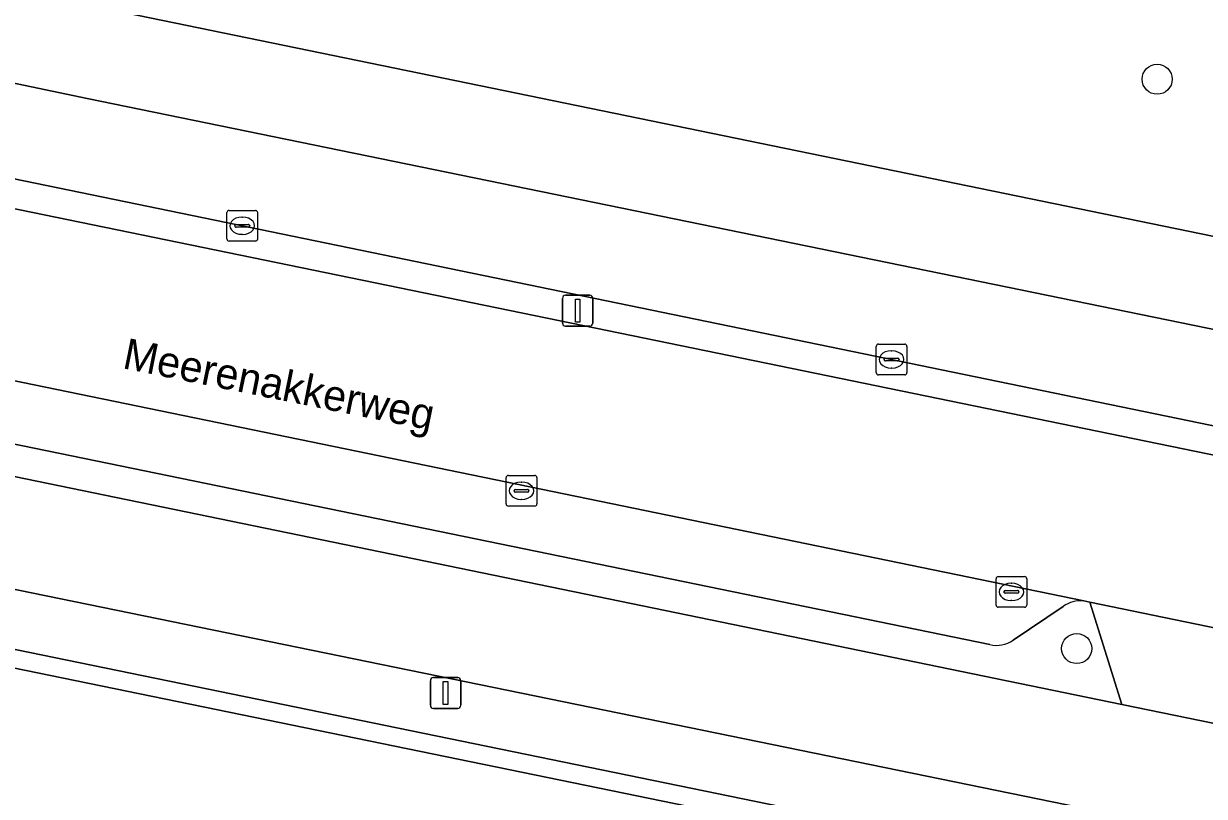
# Model space of a CAD drawing. Extents: x 157692 to 159674, y 381452 to 383291.
# Drawn here: x 158620.46 to 158658.83, y 382068.81 to 382093.93 of the extents above; entities that cross this region are included whole.
import ezdxf

# ---------------------------------------------------------------- set-up
doc = ezdxf.new("R2010")
doc.units = 0
for name, color, linetype in [('IMGEO_Berm_groen', 7, 'Continuous'), ('IMGEO_Boom', 7, 'Continuous'), ('IMGEO_Erf', 7, 'Continuous'), ('IMGEO_Fietspad_gesloten', 7, 'Continuous'), ('IMGEO_Groenvoorziening', 7, 'Continuous'), ('IMGEO_Haag', 7, 'Continuous'), ('IMGEO_Kolk', 7, 'Continuous'), ('IMGEO_Lichtmast', 7, 'Continuous'), ('IMGEO_Openbare_ruimte_label', 7, 'Continuous'), ('IMGEO_Parkeervlak_open', 7, 'Continuous'), ('IMGEO_Rijbaan_lokaal_open', 7, 'Continuous'), ('IMGEO_Rijbaan_regionaal_gesloten', 7, 'Continuous'), ('IMGEO_Voetpad_open', 7, 'Continuous')]:
    doc.layers.add(name, color=color, linetype=linetype)

msp = doc.modelspace()

# ---------------------------------------------------------------- linework, layer by layer
at = {"layer": 'IMGEO_Berm_groen'}
for points in [[(158595.092, 382100.086), (158601.14, 382098.944), (158779.77, 382062.223), (158785.616, 382060.813), (158789.108, 382059.781)], [(158778.07, 382056.314), (158773.956, 382057.298), (158711.762, 382070.015), (158600.841, 382092.865), (158585.035, 382095.717)], [(158599.236, 382092.209), (158771.914, 382056.729), (158774.468, 382056.03)], [(158599.702, 382084.466), (158599.637, 382084.492), (158599.36, 382083.49), (158656.145, 382071.8), (158655.104, 382075.124), (158654.912, 382075.163)], [(158651.862, 382073.744), (158599.702, 382084.466)], [(158654.239, 382074.984), (158652.612, 382073.887)]]:
    msp.add_lwpolyline(points, dxfattribs=at)
for centre, radius, start, end in [((158654.812, 382074.184), 0.984, 84.1681, 125.6206), ((158652.074, 382074.672), 0.952, 257.1467, 304.443)]:
    msp.add_arc(centre, radius, start, end, dxfattribs=at)
at = {"layer": 'IMGEO_Boom'}
for centre in [(158657.295, 382092.122), (158654.68, 382073.617)]:
    msp.add_circle(centre, 0.489, dxfattribs=at)
at = {"layer": 'IMGEO_Erf'}
msp.add_lwpolyline([(158656.531, 382065.514), (158574.936, 382082.265)], dxfattribs=at)
at = {"layer": 'IMGEO_Fietspad_gesloten'}
for points in [[(158776.64, 382046.995), (158774.025, 382047.607), (158748.896, 382052.715), (158732.567, 382056.096), (158710.713, 382060.669), (158694.964, 382063.831), (158656.145, 382071.8), (158599.36, 382083.49), (158578.485, 382087.788), (158553.523, 382092.644), (158551.737, 382093.049), (158548.395, 382093.597), (158547.676, 382093.718)], [(158533.524, 382092.807), (158567.173, 382086.396), (158657.056, 382067.984), (158692.348, 382060.756), (158733.578, 382052.258), (158746.373, 382049.67), (158773.852, 382044.005)]]:
    msp.add_lwpolyline(points, dxfattribs=at)
at = {"layer": 'IMGEO_Groenvoorziening'}
msp.add_lwpolyline([(158539.307, 382077.53), (158544.304, 382079.926), (158549.351, 382081.923), (158553.579, 382082.999), (158557.322, 382083.532), (158561.047, 382084.02), (158565.823, 382083.768), (158570.839, 382083.106), (158574.936, 382082.265), (158656.531, 382065.514), (158658.251, 382065.165), (158658.369, 382065.753), (158656.651, 382066.102), (158575.057, 382082.853), (158570.941, 382083.698), (158565.878, 382084.366), (158561.024, 382084.622), (158557.24, 382084.126), (158553.463, 382083.589), (158549.165, 382082.495), (158544.064, 382080.476), (158539.061, 382078.078)], dxfattribs=at)
at = {"layer": 'IMGEO_Haag'}
msp.add_lwpolyline([(158539.307, 382077.53), (158544.304, 382079.926), (158549.351, 382081.923), (158553.579, 382082.999), (158557.322, 382083.532), (158561.047, 382084.02), (158565.823, 382083.768), (158570.839, 382083.106), (158574.936, 382082.265), (158656.531, 382065.514), (158658.251, 382065.165), (158658.369, 382065.753), (158656.651, 382066.102), (158575.057, 382082.853), (158570.941, 382083.698), (158565.878, 382084.366), (158561.024, 382084.622), (158557.24, 382084.126), (158553.463, 382083.589), (158549.165, 382082.495), (158544.064, 382080.476), (158539.061, 382078.078)], dxfattribs=at)
at = {"layer": 'IMGEO_Kolk'}
for p, q in [((158627.065, 382086.934), (158627.065, 382087.786)), ((158627.14, 382087.86), (158627.992, 382087.86)), ((158628.066, 382087.786), (158628.066, 382086.934)), ((158627.324, 382087.354), (158627.324, 382087.366)), ((158627.367, 382087.403), (158627.765, 382087.403)), ((158627.553, 382087.64), (158627.578, 382087.64)), ((158627.808, 382087.366), (158627.808, 382087.354)), ((158627.762, 382087.317), (158627.364, 382087.317)), ((158627.576, 382087.08), (158627.551, 382087.08)), ((158627.992, 382086.86), (158627.14, 382086.86)), ((158648.239, 382083.513), (158649.091, 382083.513)), ((158648.164, 382082.587), (158648.164, 382083.439)), ((158648.652, 382083.293), (158648.677, 382083.293)), ((158649.165, 382083.439), (158649.165, 382082.587)), ((158648.423, 382083.007), (158648.423, 382083.019)), ((158648.861, 382082.97), (158648.463, 382082.97)), ((158648.466, 382083.056), (158648.864, 382083.056)), ((158648.907, 382083.019), (158648.907, 382083.007)), ((158649.091, 382082.513), (158648.239, 382082.513)), ((158648.675, 382082.733), (158648.65, 382082.733)), ((158636.137, 382078.32), (158636.137, 382079.172)), ((158636.212, 382079.246), (158637.064, 382079.246)), ((158636.625, 382079.026), (158636.65, 382079.026)), ((158637.138, 382079.172), (158637.138, 382078.32)), ((158636.396, 382078.74), (158636.396, 382078.752)), ((158636.834, 382078.703), (158636.436, 382078.703)), ((158636.439, 382078.789), (158636.837, 382078.789)), ((158636.88, 382078.752), (158636.88, 382078.74)), ((158637.064, 382078.246), (158636.212, 382078.246)), ((158636.648, 382078.466), (158636.623, 382078.466)), ((158652.058, 382075.031), (158652.058, 382075.883)), ((158652.133, 382075.957), (158652.985, 382075.957)), ((158653.059, 382075.883), (158653.059, 382075.031)), ((158652.317, 382075.451), (158652.317, 382075.463)), ((158652.36, 382075.5), (158652.758, 382075.5)), ((158652.546, 382075.737), (158652.571, 382075.737)), ((158652.801, 382075.463), (158652.801, 382075.451)), ((158652.755, 382075.414), (158652.357, 382075.414)), ((158652.569, 382075.177), (158652.544, 382075.177)), ((158652.985, 382074.957), (158652.133, 382074.957))]:
    msp.add_line(p, q, dxfattribs=at)
for points in [[(158627.065, 382086.934), (158627.065, 382087.786)], [(158627.14, 382087.86), (158627.992, 382087.86)], [(158628.066, 382087.786), (158628.066, 382086.934)], [(158627.992, 382086.86), (158627.14, 382086.86)], [(158648.239, 382083.513), (158649.091, 382083.513)], [(158648.164, 382082.587), (158648.164, 382083.439)], [(158649.165, 382083.439), (158649.165, 382082.587)], [(158649.091, 382082.513), (158648.239, 382082.513)], [(158636.137, 382078.32), (158636.137, 382079.172)], [(158636.212, 382079.246), (158637.064, 382079.246)], [(158637.138, 382079.172), (158637.138, 382078.32)], [(158637.064, 382078.246), (158636.212, 382078.246)], [(158652.058, 382075.031), (158652.058, 382075.883)], [(158652.133, 382075.957), (158652.985, 382075.957)], [(158653.059, 382075.883), (158653.059, 382075.031)], [(158652.985, 382074.957), (158652.133, 382074.957)]]:
    msp.add_lwpolyline(points, dxfattribs=at)
for centre, radius, start, end in [((158627.142, 382087.784), 0.0765, 91.552, 178.448), ((158627.142, 382087.784), 0.0765, 91.552, 178.448), ((158627.99, 382087.784), 0.0765, 1.552, 88.448), ((158627.99, 382087.784), 0.0765, 1.552, 88.448), ((158627.364, 382087.363), 0.0403, 85.8775, 175.7526), ((158627.361, 382087.353), 0.0366, 178.938, 274.7102), ((158627.765, 382087.36), 0.043, 264.8664, 352.4533), ((158627.769, 382087.365), 0.0386, 1.7309, 96.639), ((158627.142, 382086.936), 0.0765, 181.552, 268.448), ((158627.142, 382086.936), 0.0765, 181.552, 268.448), ((158627.99, 382086.936), 0.0765, 271.552, 358.448), ((158627.99, 382086.936), 0.0765, 271.552, 358.448), ((158648.241, 382083.437), 0.0765, 91.552, 178.448), ((158648.241, 382083.437), 0.0765, 91.552, 178.448), ((158649.089, 382083.437), 0.0765, 1.552, 88.448), ((158649.089, 382083.437), 0.0765, 1.552, 88.448), ((158648.463, 382083.016), 0.0403, 85.8775, 175.7526), ((158648.46, 382083.006), 0.0366, 178.938, 274.7102), ((158648.864, 382083.013), 0.043, 264.8664, 352.4533), ((158648.868, 382083.018), 0.0386, 1.7309, 96.639), ((158648.241, 382082.589), 0.0765, 181.552, 268.448), ((158648.241, 382082.589), 0.0765, 181.552, 268.448), ((158649.089, 382082.589), 0.0765, 271.552, 358.448), ((158649.089, 382082.589), 0.0765, 271.552, 358.448), ((158636.214, 382079.17), 0.0765, 91.552, 178.448), ((158636.214, 382079.17), 0.0765, 91.552, 178.448), ((158637.062, 382079.17), 0.0765, 1.552, 88.448), ((158637.062, 382079.17), 0.0765, 1.552, 88.448), ((158636.436, 382078.749), 0.0403, 85.8775, 175.7526), ((158636.433, 382078.739), 0.0366, 178.938, 274.7102), ((158636.837, 382078.746), 0.043, 264.8664, 352.4533), ((158636.841, 382078.751), 0.0386, 1.7309, 96.639), ((158636.214, 382078.322), 0.0765, 181.552, 268.448), ((158636.214, 382078.322), 0.0765, 181.552, 268.448), ((158637.062, 382078.322), 0.0765, 271.552, 358.448), ((158637.062, 382078.322), 0.0765, 271.552, 358.448), ((158652.135, 382075.881), 0.0765, 91.552, 178.448), ((158652.135, 382075.881), 0.0765, 91.552, 178.448), ((158652.983, 382075.881), 0.0765, 1.552, 88.448), ((158652.983, 382075.881), 0.0765, 1.552, 88.448), ((158652.357, 382075.46), 0.0403, 85.8775, 175.7526), ((158652.354, 382075.45), 0.0366, 178.938, 274.7102), ((158652.758, 382075.457), 0.043, 264.8664, 352.4533), ((158652.762, 382075.462), 0.0386, 1.7309, 96.639), ((158652.135, 382075.033), 0.0765, 181.552, 268.448), ((158652.135, 382075.033), 0.0765, 181.552, 268.448), ((158652.983, 382075.033), 0.0765, 271.552, 358.448), ((158652.983, 382075.033), 0.0765, 271.552, 358.448)]:
    msp.add_arc(centre, radius, start, end, dxfattribs=at)
for centre, major_axis, ratio, start_param, end_param in [((158627.552, 382087.36), (-0.387, 0.002), 0.722429, 4.712389, 7.853982), ((158627.577, 382087.36), (-0.39, 0.002), 0.717154, 1.570796, 4.712389), ((158648.651, 382083.013), (-0.387, 0.002), 0.722429, 4.712389, 7.853982), ((158648.676, 382083.013), (-0.39, 0.002), 0.717154, 1.570796, 4.712389), ((158636.624, 382078.746), (-0.387, 0.002), 0.722429, 4.712389, 7.853982), ((158636.649, 382078.746), (-0.39, 0.002), 0.717154, 1.570796, 4.712389), ((158652.545, 382075.457), (-0.387, 0.002), 0.722429, 4.712389, 7.853982), ((158652.57, 382075.457), (-0.39, 0.002), 0.717154, 1.570796, 4.712389)]:
    msp.add_ellipse(centre, major_axis=major_axis, ratio=ratio, start_param=start_param, end_param=end_param, dxfattribs=at)
at = {"layer": 'IMGEO_Lichtmast'}
for p, q in [((158638.069, 382085.098), (158638.859, 382085.098)), ((158638.859, 382085.098), (158638.069, 382085.098)), ((158637.969, 382084.198), (158637.969, 382084.998)), ((158637.969, 382084.998), (158637.969, 382084.198)), ((158638.959, 382084.998), (158638.959, 382084.198)), ((158638.959, 382084.198), (158638.959, 382084.998)), ((158638.859, 382084.098), (158638.069, 382084.098)), ((158638.069, 382084.098), (158638.859, 382084.098)), ((158633.679, 382071.771), (158633.679, 382072.571)), ((158633.679, 382072.571), (158633.679, 382071.771)), ((158633.779, 382072.671), (158634.569, 382072.671)), ((158634.569, 382072.671), (158633.779, 382072.671)), ((158634.669, 382072.571), (158634.669, 382071.771)), ((158634.669, 382071.771), (158634.669, 382072.571)), ((158634.569, 382071.671), (158633.779, 382071.671)), ((158633.779, 382071.671), (158634.569, 382071.671))]:
    msp.add_line(p, q, dxfattribs=at)
for points in [[(158638.389, 382084.973), (158638.539, 382084.973), (158638.539, 382084.223), (158638.389, 382084.223), (158638.389, 382084.973)], [(158634.099, 382072.546), (158634.249, 382072.546), (158634.249, 382071.796), (158634.099, 382071.796), (158634.099, 382072.546)]]:
    msp.add_lwpolyline(points, dxfattribs=at)
for centre, start, end in [((158638.069, 382084.998), 90, 180), ((158638.069, 382084.998), 90, 180), ((158638.859, 382084.998), 0, 90), ((158638.859, 382084.998), 360, 90), ((158638.069, 382084.198), 180, 270), ((158638.069, 382084.198), 180, 270), ((158638.859, 382084.198), 270, 0), ((158638.859, 382084.198), 270, 0), ((158633.779, 382072.571), 90, 180), ((158633.779, 382072.571), 90, 180), ((158634.569, 382072.571), 0, 90), ((158634.569, 382072.571), 360, 90), ((158633.779, 382071.771), 180, 270), ((158633.779, 382071.771), 180, 270), ((158634.569, 382071.771), 270, 0), ((158634.569, 382071.771), 270, 0)]:
    msp.add_arc(centre, 0.1, start, end, dxfattribs=at)
at = {"layer": 'IMGEO_Parkeervlak_open'}
for points in [[(158654.912, 382075.163), (158597.523, 382086.973)], [(158599.637, 382084.492), (158599.702, 382084.466), (158651.862, 382073.744)], [(158652.612, 382073.887), (158654.239, 382074.984)]]:
    msp.add_lwpolyline(points, dxfattribs=at)
for centre, radius, start, end in [((158654.812, 382074.184), 0.984, 84.1681, 125.6206), ((158652.074, 382074.672), 0.952, 257.1467, 304.443)]:
    msp.add_arc(centre, radius, start, end, dxfattribs=at)
at = {"layer": 'IMGEO_Rijbaan_lokaal_open'}
for points in [[(158774.468, 382056.03), (158771.914, 382056.729), (158599.236, 382092.209)], [(158592.313, 382088.012), (158597.523, 382086.973), (158654.912, 382075.163), (158655.104, 382075.124), (158697.271, 382066.421), (158697.585, 382066.362), (158731.159, 382059.515), (158751.861, 382055.219), (158752.461, 382055.052), (158771.129, 382051.26)]]:
    msp.add_lwpolyline(points, dxfattribs=at)
msp.add_lwpolyline([(158655.104, 382075.124), (158656.145, 382071.8), (158694.964, 382063.831), (158697.271, 382066.421)], close=True, dxfattribs=at)
at = {"layer": 'IMGEO_Rijbaan_regionaal_gesloten'}
for points in [[(158578.391, 382102.689), (158550.201, 382106.038), (158546.98, 382106.438), (158543.104, 382106.886), (158542.731, 382103.96), (158549.755, 382103.091), (158552.923, 382102.699), (158554.031, 382102.561), (158583.058, 382099.038), (158587.099, 382098.457), (158589.111, 382098.117), (158590.801, 382097.831), (158594.654, 382097.166), (158598.418, 382096.431), (158606.057, 382094.876), (158609.848, 382094.151), (158622.531, 382091.496), (158694.915, 382076.653)], [(158589.111, 382098.117), (158587.099, 382098.457), (158583.058, 382099.038), (158554.031, 382102.561), (158552.923, 382102.699), (158549.755, 382103.091), (158542.731, 382103.96), (158542.34, 382100.899), (158546.212, 382100.441), (158549.3, 382100.078), (158555.508, 382099.332), (158576.858, 382096.793), (158585.035, 382095.717), (158600.841, 382092.865), (158711.762, 382070.015), (158773.956, 382057.298), (158778.07, 382056.314)], [(158789.108, 382059.781), (158785.616, 382060.813), (158779.77, 382062.223), (158601.14, 382098.944), (158595.092, 382100.086)], [(158694.915, 382076.653), (158622.531, 382091.496), (158609.848, 382094.151), (158606.057, 382094.876), (158598.418, 382096.431), (158594.654, 382097.166), (158590.801, 382097.831), (158589.111, 382098.117)]]:
    msp.add_lwpolyline(points, dxfattribs=at)
at = {"layer": 'IMGEO_Voetpad_open'}
msp.add_lwpolyline([(158533.535, 382090.81), (158556.81, 382086.425), (158567.095, 382084.488), (158570.941, 382083.698), (158575.057, 382082.853), (158656.651, 382066.102), (158657.056, 382067.984), (158567.173, 382086.396)], dxfattribs=at)

# ---------------------------------------------------------------- texts
at = {"layer": 'IMGEO_Openbare_ruimte_label'}
msp.add_text('Meerenakkerweg', height=1, rotation=348.5777, dxfattribs=at).set_placement((158623.639, 382082.735))

doc.saveas('drawing.dxf')
